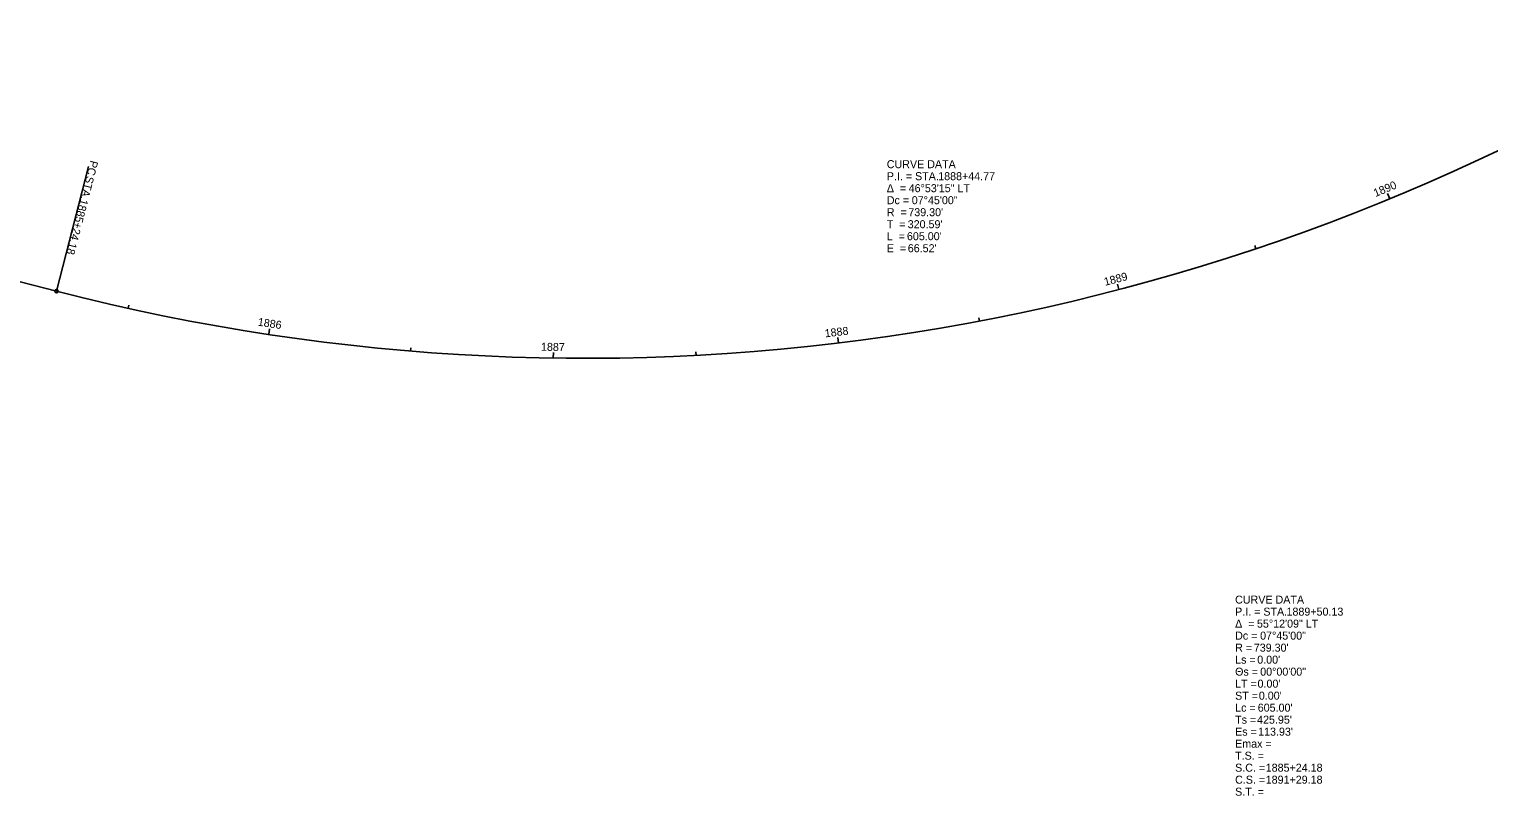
# Model space of a CAD drawing. Extents: x 199310 to 201359, y 391748 to 392909.
# Drawn here: x 200323 to 200834, y 392273 to 392541 of the extents above; entities that cross this region are included whole.
import ezdxf

# ---------------------------------------------------------------- set-up
doc = ezdxf.new("R2010")
doc.units = 0
for name, color, linetype in [('GE_X_Alignment_1000_Stations', 7, 'Continuous'), ('GE_X_Alignment_100_Stations', 7, 'Continuous'), ('GE_X_Alignment_500_Curve_Data', 7, 'Continuous'), ('GE_X_Alignment_500_Stations', 7, 'Continuous')]:
    doc.layers.add(name, color=color, linetype=linetype)

msp = doc.modelspace()

# ---------------------------------------------------------------- linework, layer by layer
at = {"layer": 'GE_X_Alignment_1000_Stations'}
for p, q in [((200799.4, 392482.01), (200798.63, 392483.86)), ((200752.56, 392464.54), (200752.18, 392465.67)), ((200704.65, 392450.27), (200704.14, 392452.2)), ((200357.97, 392443.71), (200358.23, 392444.89)), ((200655.88, 392439.27), (200655.66, 392440.45)), ((200407.12, 392434.57), (200407.42, 392436.55)), ((200606.48, 392431.59), (200606.24, 392433.58)), ((200456.77, 392428.76), (200456.87, 392429.96)), ((200506.7, 392426.33), (200506.73, 392428.33)), ((200556.68, 392427.27), (200556.62, 392428.47))]:
    msp.add_line(p, q, dxfattribs=at)
at = {"layer": 'GE_X_Alignment_100_Stations'}
msp.add_line((200040.57, 392525.22), (200332.86, 392449.73), dxfattribs=at)
msp.add_arc((200517.72, 393165.55), 739.3, 255.51964, 302.40716, dxfattribs=at)
at = {"layer": 'GE_X_Alignment_500_Stations'}
msp.add_line((200332.86, 392449.73), (200344.11, 392493.3), dxfattribs=at)
msp.add_circle((200332.86, 392449.73), 0.6, dxfattribs=at)

# ---------------------------------------------------------------- texts
at = {"layer": 'GE_X_Alignment_1000_Stations'}
for s, rotation, p in [('1890', 22.3957, (200794.39, 392482.65)), ('1889', 14.6457, (200699.81, 392451.59)), ('1886', 351.3957, (200403.17, 392437.69)), ('1888', 6.8957, (200601.85, 392433.55)), ('1887', 359.1457, (200502.38, 392428.89))]:
    msp.add_text(s, height=2.8, rotation=rotation, dxfattribs=at).set_placement(p)
at = {"layer": 'GE_X_Alignment_500_Curve_Data'}
for s, p in [('CURVE DATA', (200623.4, 392492.76)), ('P.I. = STA. ', (200623.4, 392488.56)), ('1888+44.77', (200641.39, 392488.56)), ('Δ  = ', (200623.4, 392484.36)), ('Dc = ', (200623.4, 392480.16)), ('46°53\'15" LT', (200631.05, 392484.36)), ('07°45\'00"', (200632.14, 392480.16)), ('R  = ', (200623.4, 392475.96)), ("739.30'", (200630.93, 392475.96)), ('T  = ', (200623.4, 392471.76)), ("320.59'", (200630.72, 392471.76)), ('L  = ', (200623.4, 392467.56)), ("605.00'", (200630.44, 392467.56)), ('E  = ', (200623.4, 392463.36)), ("66.52'", (200630.74, 392463.36)), ('CURVE DATA', (200745.28, 392340.42)), ('Δ  = ', (200745.28, 392332.02)), ('P.I. = STA. ', (200745.28, 392336.22)), ('55°12\'09" LT', (200752.93, 392332.02)), ('1889+50.13', (200763.27, 392336.22)), ('Dc = ', (200745.28, 392327.82)), ('07°45\'00"', (200754.03, 392327.82)), ('R = ', (200745.28, 392323.62)), ("739.30'", (200751.82, 392323.62)), ('Ls = ', (200745.28, 392319.42)), ("0.00'", (200753.03, 392319.42)), ('Θs = ', (200745.28, 392315.22)), ('00°00\'00"', (200754.07, 392315.22)), ('ST = ', (200745.28, 392306.82)), ('LT = ', (200745.28, 392311.02)), ("0.00'", (200753.13, 392311.02)), ("0.00'", (200753.58, 392306.82)), ('Lc = ', (200745.28, 392302.62)), ("605.00'", (200753.2, 392302.62)), ('Ts = ', (200745.28, 392298.42)), ("425.95'", (200752.97, 392298.42)), ('Es = ', (200745.28, 392294.22)), ("113.93'", (200753.34, 392294.22)), ('T.S. = ', (200745.28, 392285.82)), ('Emax = ', (200745.28, 392290.02)), ('S.C. = ', (200745.28, 392281.62)), ('1885+24.18', (200755.99, 392281.62)), ('C.S. = ', (200745.28, 392277.42)), ('1891+29.18', (200755.99, 392277.42)), ('S.T. = ', (200745.28, 392273.22))]:
    msp.add_text(s, height=2.8, dxfattribs=at).set_placement(p)
at = {"layer": 'GE_X_Alignment_500_Stations'}
for s, p in [('PC', (200344.76, 392495.65)), (' STA. ', (200343.61, 392491.2)), ('1885+24.18', (200341.28, 392482.17))]:
    msp.add_text(s, height=2.8, rotation=255.5196, dxfattribs=at).set_placement(p)

doc.saveas('drawing.dxf')
